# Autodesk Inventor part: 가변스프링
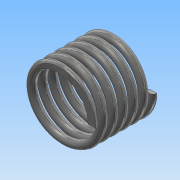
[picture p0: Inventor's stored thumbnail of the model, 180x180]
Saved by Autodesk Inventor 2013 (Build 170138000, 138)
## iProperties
Created: 2019-07
Part Number: 가변스프링
Material: 강철, 탄소
Document SubType Name: Modeling
Designer: Administrator
Density: 7.87 g/cm^3
Mass: 7.70153 g
Surface Area: 19.9894 cm^2
Volume: 0.978593 cm^3
Author: Administrator
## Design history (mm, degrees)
sketch "스케치1"
  geometry: L1 (0, 0)-(0, 16); L2 (0, 16)-(16.881, 16); C1 r 1 at (8.5, 0)
  constraints: 4 end point, 1 centre point, 1 horizontal alignment, 1 perpendicular, 1 vertical
  dimensions: "d0" = 16 distance of L1.start L1.end (derived); "d1" = 2 diameter of C1; "d2" = 17 diameter of C1.centre L1
feature "코일1" sketch "스케치1" pitch "d3" = 10; turns "d5" = 6; dims "d4" = 16 (= d0), "d6" = 0, angle "d7" = 90 deg, angle "d8" = 90 deg, "d9" = 0, "d10" = 0
sketch "스케치2"
  geometry: L1 (0, 12.5)-(16, 12.5); L2 (16, 12.5)-(16, -12.5); L3 (16, -12.5)-(0, -12.5); L4 (0, -12.5)-(0, 12.5); 2 further points
  constraints: 8 end point, 2 parallel, 1 coincident, 1 horizontal, 1 midpoint, 1 perpendicular
  dimensions: "d11" = 16 distance between parallel lines of L2 L4 (derived); "d13" = 25 distance between parallel lines of L1 L3
extrude "돌출1" sketch "스케치2" stored distance "d14" = 50; taper "d15" = 0 deg
node "솔리드1"
